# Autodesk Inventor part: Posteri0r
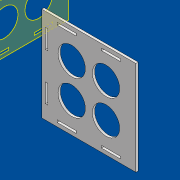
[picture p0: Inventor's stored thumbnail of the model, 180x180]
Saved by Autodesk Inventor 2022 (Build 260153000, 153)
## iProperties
Created: 2022-05
Part Number: Posteri0r
Material: Generic
Document SubType Name: Modeling
Designer: Daniel
Density: 1 g/cm^3
Appearance: Default
Author: Daniel
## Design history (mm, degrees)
sketch "Sketch1"
  geometry: L1 (65, 4)-(65, -96) reference; L2 (-35, 4)-(65, 4) reference; L3 (-35, -96)-(-35, 4) reference; L4 (65, -96)-(-35, -96) reference; L5 (48.5, 0)-(28.5, 0) reference; L6 (48.5, -2.5)-(48.5, 0) reference; L7 (28.5, -2.5)-(48.5, -2.5) reference; L8 (28.5, 0)-(28.5, -2.5) reference; L9 (1.5, -2.5)-(1.5, 0) reference; L10 (-18.5, -2.5)-(1.5, -2.5) reference; L11 (-18.5, 0)-(-18.5, -2.5) reference; L12 (1.5, 0)-(-18.5, 0) reference; L13 (-31, -11)-(-31, -31) reference; L14 (-28.5, -11)-(-31, -11) reference; L15 (-28.5, -31)-(-28.5, -11) reference; L16 (-31, -31)-(-28.5, -31) reference; L17 (-31, -61)-(-31, -81) reference; L18 (-28.5, -61)-(-31, -61) reference; L19 (-28.5, -81)-(-28.5, -61) reference; L20 (-31, -81)-(-28.5, -81) reference; L21 (28.5, -89.5)-(28.5, -92) reference; L22 (48.5, -89.5)-(28.5, -89.5) reference; L23 (48.5, -92)-(48.5, -89.5) reference; L24 (28.5, -92)-(48.5, -92) reference; L25 (-18.5, -92)-(1.5, -92) reference; L26 (-18.5, -89.5)-(-18.5, -92) reference; L27 (1.5, -89.5)-(-18.5, -89.5) reference; L28 (1.5, -92)-(1.5, -89.5) reference; C1 r 6.5 at (-3.214, -64.214) reference; C2 r 6.5 at (-3.214, -27.786) reference; C3 r 6.5 at (33.214, -27.786) reference; C4 r 6.5 at (33.214, -64.214) reference; C5 r 14.5 at (33.214, -64.214); C6 r 14.5 at (-3.214, -64.214); C7 r 14.5 at (-3.214, -27.786); C8 r 14.5 at (33.214, -27.786); 1 further point
  constraints: 4 centre point, 4 coincident
  dimensions: "d0" = 29 diameter of C5; "d1" = 29 diameter of C6; "d2" = 29 diameter of C7; "d3" = 29 diameter of C8
extrude "Extrusion1" new body sketch "Sketch1" distance "d4" = 2.5; taper "d5" = 0 deg
body "Solid1"
node "Reference1"
